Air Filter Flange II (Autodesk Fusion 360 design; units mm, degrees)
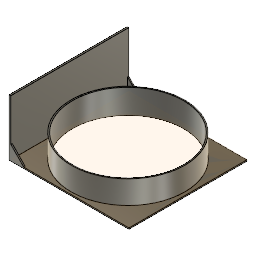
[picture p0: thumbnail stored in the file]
box_primitive "BoxPrimitive1" DistanceX 128 DistanceY 130 DistanceZ 1.5 OffsetDistanceX 0 OffsetDistanceY 0
cylinder_primitive "CylinderPrimitive1" Height 25 Diameter 123
hole "Hole1" HoleDepth 27 HoleDiameter 120 TipAngle 118
box_primitive "BoxPrimitive2" DistanceX 128 DistanceY 2 DistanceZ 60 OffsetDistanceX 0 OffsetDistanceY 0
sketch "Sketch5" plane through (0, 0, 0) normal (0, 1, 0) x axis (1, 0, 0)
extrude "Extrude1" add sketch "Sketch5" along normal blind 1.5
move_face "MoveFace1"
sketch "Sketch6" plane through (0, 0, 1.5) normal (0, 0, 1) x axis (-1, 0, 0)
sketch "Sketch7" plane through (0, 128, 0) normal (0, 1, 0) x axis (-1, 0, 0)
extrude "Extrude2" add sketch "Sketch7" against normal blind 1.5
